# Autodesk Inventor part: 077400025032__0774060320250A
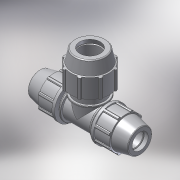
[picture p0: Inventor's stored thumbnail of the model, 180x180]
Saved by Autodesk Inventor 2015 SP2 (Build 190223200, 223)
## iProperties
Created: 2017-02
Part Number: 077400025032__0774060320250A
Material: PVC-Piping
Document SubType Name: Modeling
Designer: KIM
Mass: 92.6774 g
Surface Area: 199.44 cm^2
Volume: 66.1981 cm^3
Density: 1.4 g/cm^3
Appearance: Smooth - White
Author: KIM
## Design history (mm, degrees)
derived "07740.ipt"
feature "Solid1::07740.ipt"
tag "TaggingFeature1"
body "Solid1"
other parameters: "d2" = 25, "d4" = 7.25, "d5" = 21.84, "d7" = 54, "d9" = 12.42857, "d11" = 2.6, "d13" = 120 deg, "d14" = 37.5, "d15" = 12 deg, "d16" = 46.98, "d18" = 1.25, "d19" = 35 deg, "d20" = 17.5 deg, "d21" = 50.22, "d23" = 0, "d25" = 360 deg, "d27" = 1.08, "d33" = 0.5, "d42" = 28.08, "d43" = 1.62, "d46" = 0.75, "d67" = 40.5, "d76" = 32, "d77" = 64, "d78" = 12 deg, "d79" = 87, "d80" = 120 deg, "d81" = 48, "d82" = 6.25, "d85" = 40.5, "d87" = 2.5, "d89" = 18.75, "d96" = 4.68, "d98" = 59.52, "d99" = 35 deg, "d100" = 17.5 deg, "d102" = 0, "d103" = 1.28, "d107" = 360 deg, "d109" = 0.96, "d112" = 1.6, "d113" = 4.26667, "d114" = 0, "d117" = 156, "d118" = 51.2, "d126" = 22.5, "d127" = 58, "d131" = 12.18, "d132" = 22.5, "d133" = 69, "d135" = 0, "d138" = 3.12, "d139" = 44.8, "d141" = 0, "d143" = 0, "d145" = 0, "d147" = 0, "d_" = 25, "E_" = 54, "A_" = 87, "l_" = 58, "E_1" = 64, "l_1" = 69, "A_1" = 75, "d_1" = 32, "H_" = 156
